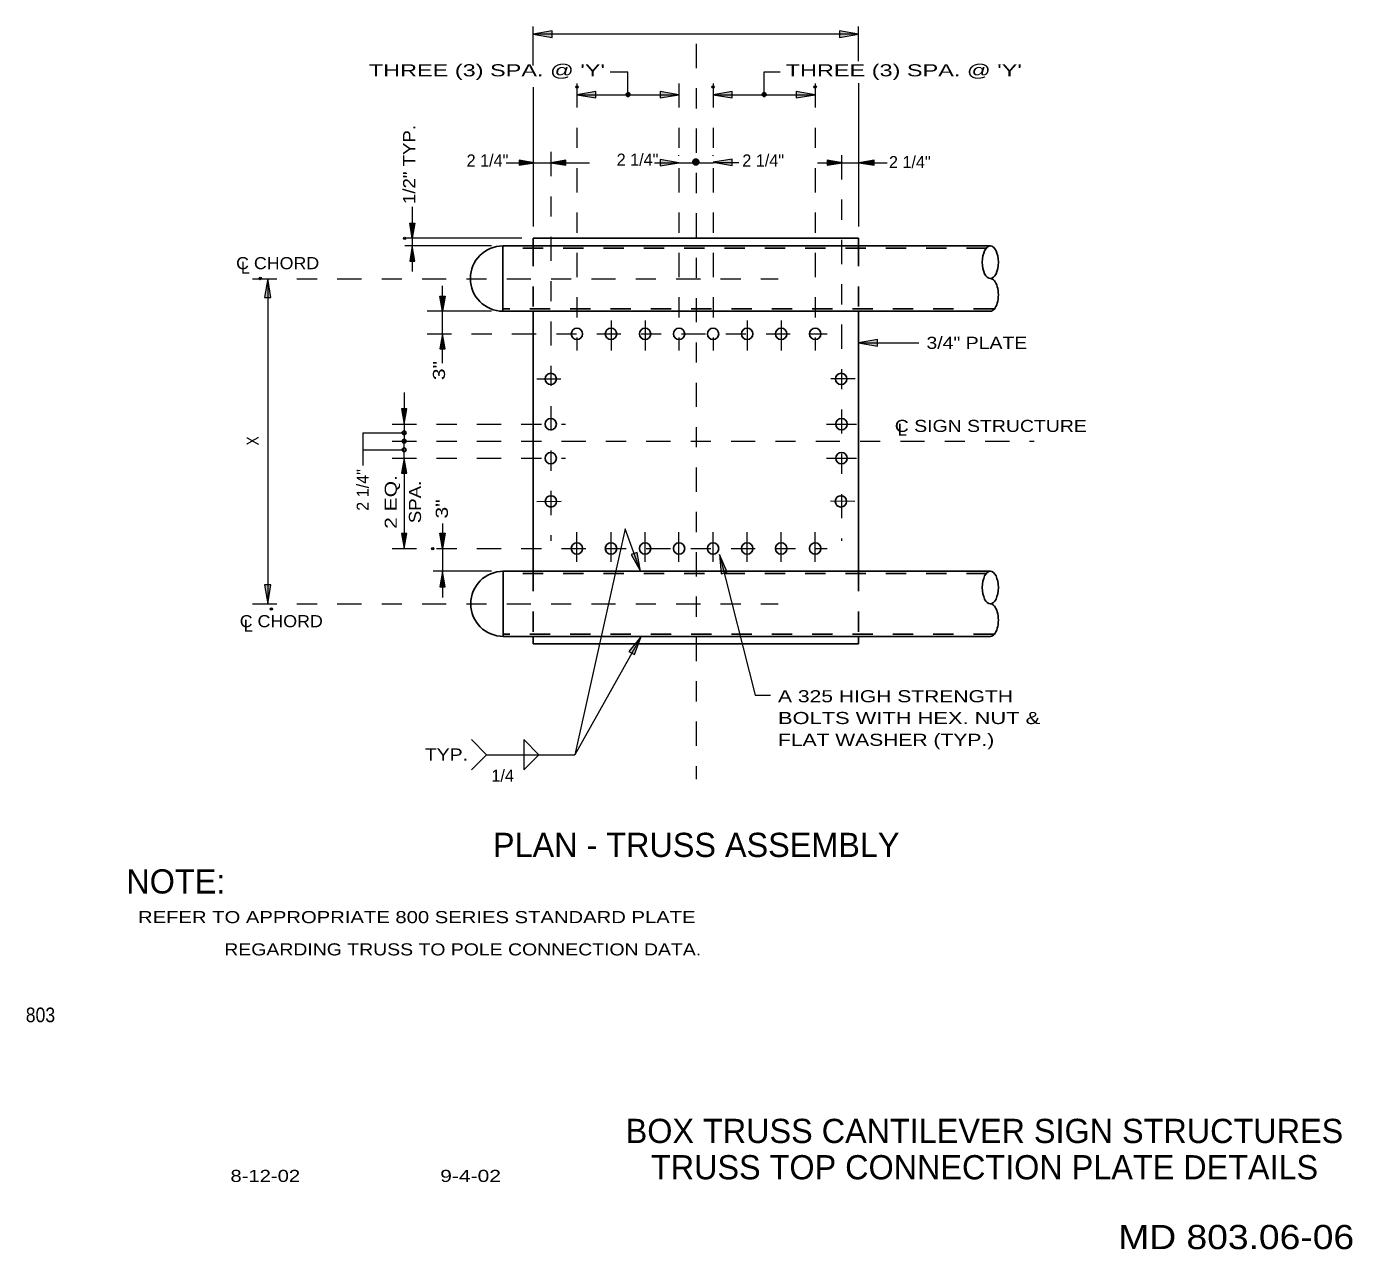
# Model space of a CAD drawing. Extents: x -34838.8 to -34832.2, y -181512.9 to -181502.8.
# Drawn here: x -34838.79 to -34832.22, y -181512.92 to -181506.85 of the extents above; entities that cross this region are included whole.
import ezdxf
from ezdxf.enums import TextEntityAlignment as Align

# ---------------------------------------------------------------- set-up
doc = ezdxf.new("R2010")
doc.units = 0
doc.header["$LTSCALE"] = 0.024
doc.header["$PDMODE"] = 32
doc.header["$PDSIZE"] = 0.012
doc.linetypes.add('DOT_DASHED', pattern=[7.7, 5, -1.2, 0.3, -1.2])
doc.linetypes.add('MEDIUM_DASHED', pattern=[4.5, 3, -1.5])
doc.layers.add('1', color=7, linetype='Continuous', lineweight=25)
doc.layers.add('10', color=7, linetype='Continuous', lineweight=13)
doc.layers.add('12', color=7, linetype='Continuous')
doc.layers.add('13', color=7, linetype='Continuous')

msp = doc.modelspace()

# ---------------------------------------------------------------- hatches: boundary and pattern name
at = {"layer": '1'}
for points in [[(-34835.79932, -181507.19077, 1), (-34835.81807, -181507.19077, 1)], [(-34835.12432, -181507.19077, 1), (-34835.14307, -181507.19077, 1)], [(-34835.45773, -181507.52449, 1), (-34835.48702, -181507.52449, 1)]]:
    msp.add_hatch(color=256, dxfattribs=at).paths.add_polyline_path(points)
at = {"layer": '10'}
for points in [[(-34836.185, -181506.907), (-34836.185, -181506.875), (-34836.279, -181506.891)], [(-34836.185, -181506.907), (-34836.185, -181506.875), (-34836.279, -181506.891)], [(-34834.76, -181506.875), (-34834.76, -181506.907), (-34834.666, -181506.891)], [(-34834.76, -181506.875), (-34834.76, -181506.907), (-34834.666, -181506.891)], [(-34835.968, -181507.207), (-34835.968, -181507.175), (-34836.062, -181507.191)], [(-34835.65, -181507.175), (-34835.65, -181507.207), (-34835.556, -181507.191)], [(-34835.293, -181507.207), (-34835.293, -181507.175), (-34835.387, -181507.191)], [(-34834.975, -181507.175), (-34834.975, -181507.207), (-34834.881, -181507.191)], [(-34836.349, -181507.541), (-34836.274, -181507.528), (-34836.349, -181507.516)], [(-34836.117, -181507.516), (-34836.192, -181507.528), (-34836.117, -181507.541)], [(-34835.65, -181507.512), (-34835.65, -181507.544), (-34835.556, -181507.528)], [(-34835.293, -181507.542), (-34835.293, -181507.51), (-34835.387, -181507.526)], [(-34834.821, -181507.541), (-34834.746, -181507.528), (-34834.821, -181507.516)], [(-34834.589, -181507.516), (-34834.664, -181507.528), (-34834.589, -181507.541)], [(-34836.866, -181507.828), (-34836.879, -181507.903), (-34836.891, -181507.828)], [(-34836.866, -181508.016), (-34836.879, -181507.941), (-34836.891, -181508.016)], [(-34837.611, -181508.196), (-34837.579, -181508.196), (-34837.595, -181508.102)], [(-34837.611, -181508.196), (-34837.579, -181508.196), (-34837.595, -181508.102)], [(-34836.716, -181508.189), (-34836.729, -181508.264), (-34836.741, -181508.189)], [(-34836.716, -181508.451), (-34836.729, -181508.376), (-34836.741, -181508.451)], [(-34834.572, -181508.437), (-34834.572, -181508.405), (-34834.666, -181508.421)], [(-34836.906, -181508.749), (-34836.932, -181508.749), (-34836.919, -181508.824)], [(-34836.932, -181509.068), (-34836.906, -181509.068), (-34836.919, -181508.993)], [(-34836.906, -181509.366), (-34836.932, -181509.366), (-34836.919, -181509.441)], [(-34836.716, -181509.365), (-34836.729, -181509.44), (-34836.741, -181509.365)], [(-34835.763, -181509.46), (-34835.793, -181509.47), (-34835.746, -181509.553)], [(-34835.347, -181509.566), (-34835.317, -181509.558), (-34835.355, -181509.471)], [(-34836.716, -181509.63), (-34836.729, -181509.555), (-34836.741, -181509.63)], [(-34837.579, -181509.621), (-34837.611, -181509.621), (-34837.595, -181509.715)], [(-34835.804, -181509.951), (-34835.776, -181509.966), (-34835.744, -181509.877)]]:
    msp.add_hatch(color=256, dxfattribs=at).paths.add_polyline_path(points)

# ---------------------------------------------------------------- linework, layer by layer
at = {"layer": '1', "linetype": 'DOT_DASHED', "lineweight": 13}
for p, q in [((-34835.471, -181506.939), (-34835.471, -181510.585)), ((-34836.062, -181507.135), (-34836.062, -181508.459)), ((-34835.556, -181507.135), (-34835.556, -181508.459)), ((-34835.387, -181507.135), (-34835.387, -181508.459)), ((-34834.881, -181507.135), (-34834.881, -181508.459)), ((-34836.192, -181507.475), (-34836.192, -181509.402)), ((-34834.75, -181507.491), (-34834.75, -181509.402)), ((-34837.67, -181508.103), (-34835.065, -181508.103)), ((-34836.804, -181508.377), (-34834.822, -181508.377)), ((-34836.261, -181508.6), (-34836.118, -181508.599)), ((-34834.683, -181508.6), (-34834.826, -181508.599)), ((-34836.978, -181508.824), (-34836.118, -181508.824)), ((-34836.978, -181508.909), (-34833.795, -181508.909)), ((-34836.978, -181508.993), (-34836.118, -181508.993)), ((-34836.26, -181509.207), (-34836.117, -181509.206)), ((-34834.684, -181509.207), (-34834.827, -181509.206)), ((-34836.978, -181509.441), (-34834.822, -181509.441)), ((-34837.67, -181509.715), (-34835.065, -181509.715))]:
    msp.add_line(p, q, dxfattribs=at)
at = {"layer": '1'}
for p, q in [((-34834.666, -181507.903), (-34836.279, -181507.903)), ((-34836.279, -181507.903), (-34836.279, -181507.941)), ((-34834.666, -181507.903), (-34834.666, -181507.941)), ((-34834.012, -181507.941), (-34836.429, -181507.941)), ((-34836.429, -181507.941), (-34836.429, -181508.264)), ((-34834.012, -181508.264), (-34836.429, -181508.264)), ((-34836.279, -181508.264), (-34836.279, -181509.553)), ((-34834.666, -181508.264), (-34834.666, -181509.553)), ((-34834.012, -181509.553), (-34836.429, -181509.553)), ((-34836.427, -181509.553), (-34836.427, -181509.877)), ((-34834.012, -181509.877), (-34836.427, -181509.877)), ((-34836.279, -181509.914), (-34836.279, -181509.877)), ((-34834.666, -181509.877), (-34834.666, -181509.914)), ((-34834.666, -181509.914), (-34836.279, -181509.914))]:
    msp.add_line(p, q, dxfattribs=at)
at = {"layer": '1', "linetype": 'MEDIUM_DASHED'}
for p, q in [((-34834.03, -181507.952), (-34836.429, -181507.952)), ((-34836.279, -181507.941), (-34836.279, -181508.264)), ((-34834.666, -181507.941), (-34834.666, -181508.264)), ((-34833.995, -181508.253), (-34836.429, -181508.253)), ((-34834.03, -181509.565), (-34836.427, -181509.565)), ((-34836.279, -181509.553), (-34836.279, -181509.877)), ((-34834.666, -181509.553), (-34834.666, -181509.877)), ((-34833.995, -181509.865), (-34836.427, -181509.865))]:
    msp.add_line(p, q, dxfattribs=at)
at = {"layer": '1', "lineweight": 13}
for p, q in [((-34835.893, -181508.311), (-34835.893, -181508.459)), ((-34835.724, -181508.311), (-34835.724, -181508.459)), ((-34835.218, -181508.311), (-34835.218, -181508.459)), ((-34835.049, -181508.311), (-34835.049, -181508.459)), ((-34834.824, -181508.824), (-34834.676, -181508.824)), ((-34834.824, -181508.993), (-34834.676, -181508.993)), ((-34836.062, -181509.506), (-34836.062, -181509.359)), ((-34835.893, -181509.506), (-34835.893, -181509.359)), ((-34835.724, -181509.506), (-34835.724, -181509.359)), ((-34835.556, -181509.506), (-34835.556, -181509.359)), ((-34835.387, -181509.506), (-34835.387, -181509.359)), ((-34835.218, -181509.506), (-34835.218, -181509.359)), ((-34835.049, -181509.506), (-34835.049, -181509.359)), ((-34834.881, -181509.506), (-34834.881, -181509.359))]:
    msp.add_line(p, q, dxfattribs=at)
at = {"layer": '1'}
for centre, radius in [((-34835.8087, -181507.19077), 0.00937), ((-34835.1337, -181507.19077), 0.00937), ((-34835.47237, -181507.52449), 0.01465), ((-34836.06182, -181508.37671), 0.02813), ((-34835.89307, -181508.37671), 0.02813), ((-34835.72432, -181508.37671), 0.02813), ((-34835.55557, -181508.37671), 0.02813), ((-34835.38682, -181508.37671), 0.02813), ((-34835.21807, -181508.37671), 0.02813), ((-34835.04932, -181508.37671), 0.02813), ((-34834.88057, -181508.37671), 0.02813), ((-34836.19198, -181508.59989), 0.02813), ((-34834.75203, -181508.59989), 0.02813), ((-34836.91873, -181508.86657), 0.00937), ((-34836.19202, -181508.82439), 0.02813), ((-34834.75038, -181508.82439), 0.02813), ((-34836.91873, -181508.90876), 0.00937), ((-34836.91873, -181508.95095), 0.00937), ((-34836.19202, -181508.99314), 0.02813), ((-34834.75038, -181508.99314), 0.02813), ((-34836.19098, -181509.20689), 0.02813), ((-34834.75302, -181509.20689), 0.02813), ((-34836.06182, -181509.44081), 0.02813), ((-34835.89307, -181509.44081), 0.02813), ((-34835.72432, -181509.44081), 0.02813), ((-34835.55557, -181509.44081), 0.02813), ((-34835.38682, -181509.44081), 0.02813), ((-34835.21807, -181509.44081), 0.02813), ((-34835.04932, -181509.44081), 0.02813), ((-34834.88057, -181509.44081), 0.02813)]:
    msp.add_circle(centre, radius, dxfattribs=at)
for centre in [(-34836.42873, -181508.10247), (-34836.42666, -181509.71498)]:
    msp.add_arc(centre, 0.1617, 90, 270, dxfattribs=at)
for centre in [(-34834.0123, -181508.02164), (-34834.0123, -181509.63414)]:
    msp.add_ellipse(centre, major_axis=(0, -0.08085), ratio=0.492739, dxfattribs=at)
for centre in [(-34834.0123, -181508.18335), (-34834.0123, -181509.79585)]:
    msp.add_ellipse(centre, major_axis=(0, -0.08085), ratio=0.492739, start_param=6.2831853, end_param=9.424778, dxfattribs=at)
at = {"layer": '10'}
for p, q in [((-34836.279, -181507.047), (-34836.279, -181506.853)), ((-34834.666, -181507.025), (-34834.666, -181506.853)), ((-34834.666, -181506.891), (-34836.279, -181506.891)), ((-34835.897, -181507.078), (-34835.809, -181507.078)), ((-34835.809, -181507.191), (-34835.809, -181507.078)), ((-34835.134, -181507.191), (-34835.134, -181507.078)), ((-34835.134, -181507.078), (-34835.054, -181507.078)), ((-34834.666, -181507.133), (-34834.666, -181507.844)), ((-34836.279, -181507.154), (-34836.279, -181507.844)), ((-34836.062, -181507.191), (-34835.556, -181507.191)), ((-34835.556, -181507.172), (-34835.556, -181507.228)), ((-34835.387, -181507.191), (-34834.881, -181507.191)), ((-34836.413, -181507.528), (-34835.999, -181507.528)), ((-34835.678, -181507.528), (-34835.556, -181507.528)), ((-34835.556, -181507.494), (-34835.556, -181507.491)), ((-34835.556, -181507.528), (-34835.387, -181507.528)), ((-34835.387, -181507.494), (-34835.387, -181507.491)), ((-34835.259, -181507.528), (-34835.387, -181507.528)), ((-34834.869, -181507.528), (-34834.524, -181507.528)), ((-34836.879, -181507.747), (-34836.879, -181508.067)), ((-34836.335, -181507.903), (-34836.916, -181507.903)), ((-34836.879, -181507.941), (-34836.916, -181507.941)), ((-34836.485, -181507.941), (-34836.879, -181507.941)), ((-34837.595, -181508.102), (-34837.595, -181509.715)), ((-34836.729, -181508.522), (-34836.729, -181508.138)), ((-34836.485, -181508.264), (-34836.804, -181508.264)), ((-34836.586, -181508.264), (-34836.766, -181508.264)), ((-34836.919, -181508.668), (-34836.919, -181508.909)), ((-34837.123, -181508.867), (-34836.919, -181508.867)), ((-34837.123, -181508.867), (-34837.123, -181509.03)), ((-34836.919, -181508.993), (-34836.919, -181508.909)), ((-34837.123, -181508.951), (-34836.919, -181508.951)), ((-34836.919, -181508.993), (-34836.919, -181509.441)), ((-34836.729, -181509.316), (-34836.729, -181509.683)), ((-34836.485, -181509.553), (-34836.775, -181509.553)), ((-34836.513, -181509.553), (-34836.766, -181509.553)), ((-34835.744, -181509.877), (-34836.073, -181510.463)), ((-34836.585, -181510.388), (-34836.51, -181510.463)), ((-34836.326, -181510.388), (-34836.251, -181510.463)), ((-34836.585, -181510.538), (-34836.51, -181510.463)), ((-34836.51, -181510.463), (-34836.073, -181510.463))]:
    msp.add_line(p, q, dxfattribs=at)
for points in [[(-34836.185, -181506.907), (-34836.185, -181506.875), (-34836.279, -181506.891)], [(-34836.185, -181506.907), (-34836.185, -181506.875), (-34836.279, -181506.891)], [(-34834.76, -181506.875), (-34834.76, -181506.907), (-34834.666, -181506.891)], [(-34834.76, -181506.875), (-34834.76, -181506.907), (-34834.666, -181506.891)], [(-34835.968, -181507.207), (-34835.968, -181507.175), (-34836.062, -181507.191)], [(-34835.65, -181507.175), (-34835.65, -181507.207), (-34835.556, -181507.191)], [(-34835.293, -181507.207), (-34835.293, -181507.175), (-34835.387, -181507.191)], [(-34834.975, -181507.175), (-34834.975, -181507.207), (-34834.881, -181507.191)], [(-34836.349, -181507.541), (-34836.274, -181507.528), (-34836.349, -181507.516)], [(-34836.117, -181507.516), (-34836.192, -181507.528), (-34836.117, -181507.541)], [(-34835.65, -181507.512), (-34835.65, -181507.544), (-34835.556, -181507.528)], [(-34835.293, -181507.542), (-34835.293, -181507.51), (-34835.387, -181507.526)], [(-34834.821, -181507.541), (-34834.746, -181507.528), (-34834.821, -181507.516)], [(-34834.589, -181507.516), (-34834.664, -181507.528), (-34834.589, -181507.541)], [(-34836.866, -181507.828), (-34836.879, -181507.903), (-34836.891, -181507.828)], [(-34836.866, -181508.016), (-34836.879, -181507.941), (-34836.891, -181508.016)], [(-34837.611, -181508.196), (-34837.579, -181508.196), (-34837.595, -181508.102)], [(-34837.611, -181508.196), (-34837.579, -181508.196), (-34837.595, -181508.102)], [(-34836.716, -181508.189), (-34836.729, -181508.264), (-34836.741, -181508.189)], [(-34836.716, -181508.451), (-34836.729, -181508.376), (-34836.741, -181508.451)], [(-34834.572, -181508.437), (-34834.572, -181508.405), (-34834.666, -181508.421)], [(-34836.906, -181508.749), (-34836.932, -181508.749), (-34836.919, -181508.824)], [(-34836.932, -181509.068), (-34836.906, -181509.068), (-34836.919, -181508.993)], [(-34836.906, -181509.366), (-34836.932, -181509.366), (-34836.919, -181509.441)], [(-34836.716, -181509.365), (-34836.729, -181509.44), (-34836.741, -181509.365)], [(-34835.763, -181509.46), (-34835.793, -181509.47), (-34835.746, -181509.553)], [(-34835.347, -181509.566), (-34835.317, -181509.558), (-34835.355, -181509.471)], [(-34836.716, -181509.63), (-34836.729, -181509.555), (-34836.741, -181509.63)], [(-34837.579, -181509.621), (-34837.611, -181509.621), (-34837.595, -181509.715)], [(-34835.804, -181509.951), (-34835.776, -181509.966), (-34835.744, -181509.877)]]:
    msp.add_lwpolyline(points, close=True, dxfattribs=at)
for points in [[(-34834.666, -181508.421), (-34834.366, -181508.421), (-34834.366, -181508.421)], [(-34835.746, -181509.553), (-34835.823, -181509.343), (-34836.073, -181510.463)], [(-34835.355, -181509.471), (-34835.178, -181510.168), (-34835.103, -181510.168)], [(-34836.326, -181510.388), (-34836.326, -181510.538), (-34836.251, -181510.463)]]:
    msp.add_lwpolyline(points, dxfattribs=at)
for p in [(-34836.062, -181507.153), (-34835.387, -181507.153), (-34834.881, -181507.153), (-34836.916, -181507.903), (-34837.632, -181508.102), (-34836.777, -181509.441), (-34837.577, -181509.741)]:
    msp.add_point(p, dxfattribs=at)

# ---------------------------------------------------------------- texts
at = {"layer": '12'}
for s, p in [('PLAN - TRUSS ASSEMBLY', (-34835.4705, -181510.97)), ('NOTE:', (-34838.051, -181511.151))]:
    msp.add_text(s, height=0.12, dxfattribs=at).set_placement(p, align=Align.CENTER)
at = {"layer": '13'}
for s, height, width, p in [("THREE (3) SPA. @ 'Y'", 0.06, 1.45, (-34837.094, -181507.1)), ("THREE (3) SPA. @ 'Y'", 0.06, 1.45, (-34835.027, -181507.1)), ('3/4" PLATE', 0.06, 1.2, (-34834.329, -181508.451)), ('C SIGN STRUCTURE', 0.06, 1.2, (-34834.486, -181508.863)), ('A 325 HIGH STRENGTH ', 0.06, 1.3, (-34835.065, -181510.203)), ('BOLTS WITH HEX. NUT & ', 0.06, 1.35, (-34835.065, -181510.311)), ('FLAT WASHER (TYP.)', 0.06, 1.3, (-34835.065, -181510.419)), ('8-12-02', 0.06, 1.25, (-34837.78, -181512.581)), ('9-4-02', 0.06, 1.3, (-34836.74, -181512.581)), ('MD 803.06-06', 0.12, 1.15, (-34833.378, -181512.914))]:
    msp.add_text(s, height=height, dxfattribs=dict(at, width=width)).set_placement(p)
for s, width, p in [('1/2" TYP.', 1.15, (-34836.864, -181507.733)), ('3"', 1.3, (-34836.716, -181508.606)), ('X', 0.85, (-34837.64, -181508.93)), ('3"', 1.3, (-34836.702, -181509.292))]:
    msp.add_text(s, height=0.06, rotation=90, dxfattribs=dict(at, width=width)).set_placement(p)
for s, p in [('2 1/4"', (-34836.609, -181507.547)), ('2 1/4"', (-34835.865, -181507.543)), ('2 1/4"', (-34835.242, -181507.547)), ('2 1/4"', (-34834.515, -181507.555)), ('L', (-34837.728, -181508.079)), ('L', (-34834.471, -181508.881)), ('L', (-34837.714, -181509.853)), ('1/4', (-34836.486, -181510.597))]:
    msp.add_text(s, height=0.06, dxfattribs=at).set_placement(p)
for s, width, p in [('C CHORD', 1.1, (-34837.34, -181508.056)), ('C CHORD', 1.1, (-34837.322, -181509.831)), ('TYP.', 1.2, (-34836.602, -181510.492)), ('REFER TO APPROPRIATE 800 SERIES STANDARD PLATE ', 1.25, (-34835.446, -181511.298)), ('REGARDING TRUSS TO POLE CONNECTION DATA.', 1.2, (-34835.446, -181511.458))]:
    msp.add_text(s, height=0.06, dxfattribs=dict(at, width=width)).set_placement(p, align=Align.RIGHT)
msp.add_text('2 1/4"', height=0.06, rotation=90, dxfattribs=at).set_placement((-34837.094, -181509.254))
for s, width, p in [('2 EQ.', 1.3, (-34836.955, -181509.21)), ('SPA.', 1.15, (-34836.835, -181509.21))]:
    msp.add_text(s, height=0.06, rotation=90, dxfattribs=dict(at, width=width)).set_placement(p, align=Align.CENTER)
at = {"layer": '13', "width": 0.9}
msp.add_text('803', height=0.07251, dxfattribs=at).set_placement((-34838.722, -181511.789), align=Align.CENTER)
at = {"layer": '13'}
for s, p in [('BOX TRUSS CANTILEVER SIGN STRUCTURES', (-34834.0415, -181512.388)), ('TRUSS TOP CONNECTION PLATE DETAILS', (-34834.041, -181512.568))]:
    msp.add_text(s, height=0.12, dxfattribs=at).set_placement(p, align=Align.CENTER)

doc.saveas('drawing.dxf')
